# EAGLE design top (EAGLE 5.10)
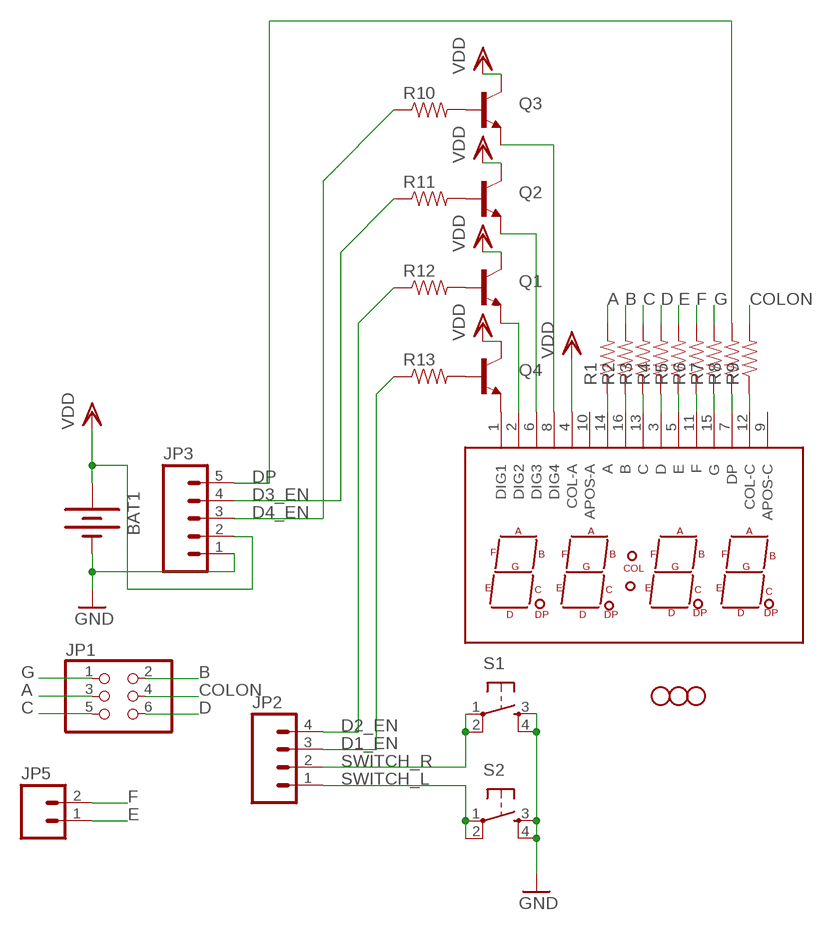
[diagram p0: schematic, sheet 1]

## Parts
BAT1  BATTERYFOB  [BATTERY_20MM_PTH_COMPACT]
JP1  PINHD-2X3  [2X03]
JP2  M04PTH  [1X04]
JP3  M05PTH  [1X05]
JP4  STAND-OFF  [STAND-OFF]
JP5  M02PTH  [1X02]
JP6  STAND-OFF  [STAND-OFF]
JP7  STAND-OFF  [STAND-OFF]
Q1  TRANSISTOR_NPNTO92  [TO-92]
Q2  TRANSISTOR_NPNTO92  [TO-92]
Q3  TRANSISTOR_NPNTO92  [TO-92]
Q4  TRANSISTOR_NPNTO92  [TO-92]
R1  RESISTORPTH-1/6W  [1/6W-RES]
R2  RESISTORPTH-1/6W  [1/6W-RES]
R3  RESISTORPTH-1/6W  [1/6W-RES]
R4  RESISTORPTH-1/6W  [1/6W-RES]
R5  RESISTORPTH-1/6W  [1/6W-RES]
R6  RESISTORPTH-1/6W  [1/6W-RES]
R7  RESISTORPTH-1/6W  [1/6W-RES]
R8  RESISTORPTH-1/6W  [1/6W-RES]
R9  RESISTORPTH-1/6W  [1/6W-RES]
R10  RESISTORPTH-1/6W  [1/6W-RES]
R11  RESISTORPTH-1/6W  [1/6W-RES]
R12  RESISTORPTH-1/6W  [1/6W-RES]
R13  RESISTORPTH-1/6W  [1/6W-RES]
S1  TAC_SWITCHPTH  [TACTILE-PTH]
S2  TAC_SWITCHPTH  [TACTILE-PTH]
U$1  7-SEGMENT-4DIGIT-YOUNGSUN  [7-SEGMENT-4DIGIT-YOUNGSUN]

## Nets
A: JP1.3 R1.2
B: JP1.2 R2.2
C: JP1.5 R3.2
COLON: JP1.4 R9.2
D: JP1.6 R4.2
D1_EN: JP2.3 R13.1
D2_EN: JP2.4 R12.1
D3_EN: JP3.4 R11.1
D4_EN: JP3.3 R10.1
DP: JP3.5 R8.2
E: JP5.1 R5.2
F: JP5.2 R6.2
G: JP1.1 R7.2
GND: BAT1.2(-) JP3.1 S1.3 S1.4 S2.3 S2.4
N$1: R1.1 U$1.14(A)
N$2: R2.1 U$1.16(B)
N$3: R3.1 U$1.13(C)
N$4: R4.1 U$1.3(D)
N$5: R5.1 U$1.5(E)
N$6: R6.1 U$1.11(F)
N$7: R7.1 U$1.15(G)
N$8: R8.1 U$1.7(DP)
N$9: Q4.1(E) U$1.1(DIG1)
N$19: R9.1 U$1.12(COL-C)
N$20: Q1.1(E) U$1.2(DIG2)
N$21: Q2.1(E) U$1.6(DIG3)
N$24: Q3.1(E) U$1.8(DIG4)
N$25: Q3.2(B) R10.2
N$26: Q2.2(B) R11.2
N$27: Q1.2(B) R12.2
N$28: Q4.2(B) R13.2
SWITCH_L: JP2.1 S2.1 S2.2
SWITCH_R: JP2.2 S1.1 S1.2
VDD: BAT1.1(+) JP3.2 Q1.3(C) Q2.3(C) Q3.3(C) Q4.3(C) U$1.4(COL-A)
Unconnected: U$1.9(APOS-C) U$1.10(APOS-A)

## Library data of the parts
BAT1 = SparkFun:BATTERY: Battery Holders
JP1 = SparkFun:PINHD-2X3: PIN HEADER
JP2 = SparkFun:M04: Header 4 Standard 4-pin 0.1" header. Use with straight break away headers (SKU : PRT-00116), right angle break away headers (PRT-00553), swiss pins (PRT-00743), machine pins (PRT-00117), and female headers (PRT-00115). Molex polarized connector foot print use with SKU : PRT-08231 with associated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
JP3 = SparkFun:M05: Header 5 Standard 5-pin 0.1" header. Use with straight break away headers (SKU : PRT-00116), right angle break away headers (PRT-00553), swiss pins (PRT-00743), machine pins (PRT-00117), and female headers (PRT-00115). Molex polarized connector foot print use with SKU : PRT-08230 with associated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
JP4 JP6 JP7 = SparkFun:STAND-OFF: Stand Off
JP5 = SparkFun:M02: Header 2
Q1-Q4 = SparkFun:TRANSISTOR_NPN: Transistor NPN BJT configuration in SOT23 package. MMBT2222 is the common NPN we use. Double check BCE configuration again layout.
R1-R13 = SparkFun:RESISTOR: Resistor
S1 S2 = SparkFun:TAC_SWITCH: Momentary Switch Button commonly used for reset or general input. Spark Fun Electronics SKU : COM-00097
U$1 = SparkFun:7-SEGMENT-4DIGIT-YOUNGSUN: This is a part for the 4-Digit 7-segment LEDs from Young Sun. Different from the Digikey LEDs, all 16 pins are used. The LONGPADS Variant is used for a test jig, but you may like it because there is more pad to solder to. If you are concerned about routing space, the standard works just fine though.

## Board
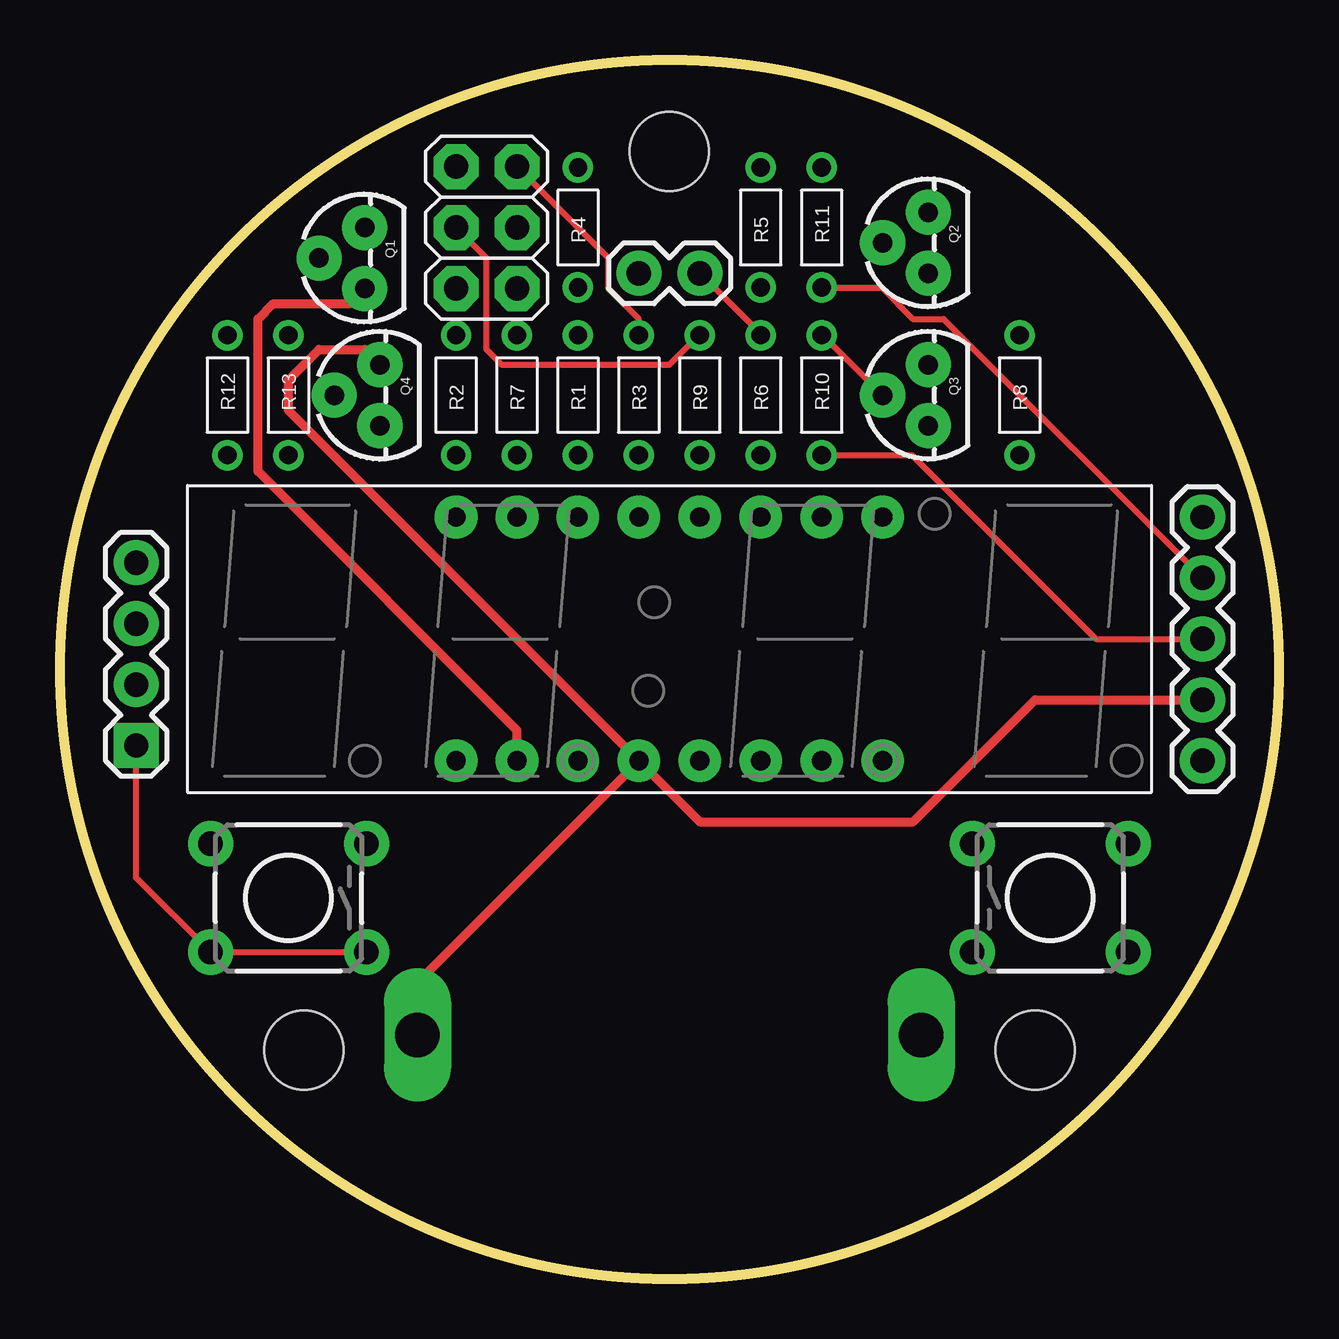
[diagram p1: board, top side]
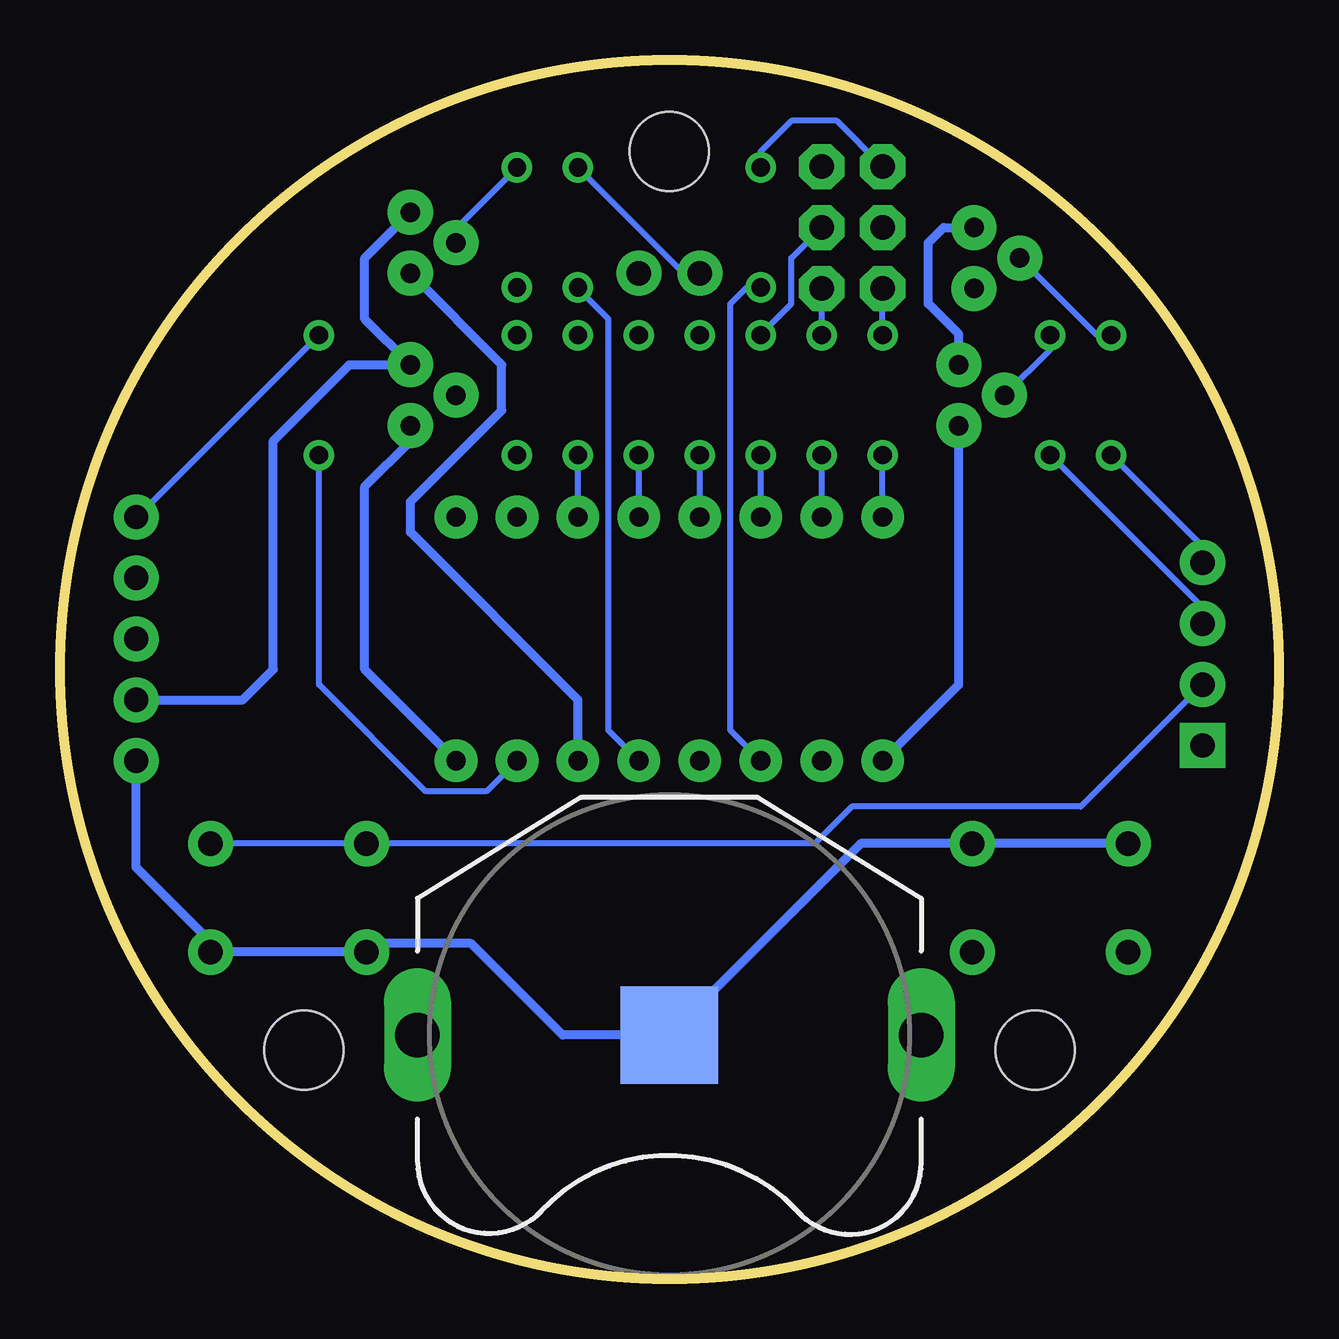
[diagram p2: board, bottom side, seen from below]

Size 50.8 x 50.8 mm. Coordinates in mm from the lower left corner, seen from the top.
Outline: circle at 25.4,25.4 radius 25.4
Copper layers (1*16): Top 0.035mm / dielectric 1.5mm / Bottom 0.035mm
Design rules "default": minimum track width 10mil, minimum drill 24mil, track to track 8mil, track to pad 8mil, pad to pad 8mil, via to via 8mil, smd to smd 8mil, copper to edge 40mil, drill to drill 8mil, minimum pad ring 10mil, minimum via ring 8mil, stop-mask expansion 4mil, vias tented up to drill 0mil, thermal gap 10mil

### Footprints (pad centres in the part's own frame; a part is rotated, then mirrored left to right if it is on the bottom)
BATTERY_20MM_PTH_COMPACT = drill 1.854 long: 1 -10.5,0; 3 10.5,0 | smd 4.064 x 4.064: 2 0,0
2X03 = drill 1.016 pad 1.88 octagon: 1 -2.54,-1.27; 2 -2.54,1.27; 3 0,-1.27; 4 0,1.27; 5 2.54,-1.27; 6 2.54,1.27
1X04 = drill 1.016 pad 1.88 square: 1 0,0 | drill 1.016 pad 1.88 round: 2 2.54,0; 3 5.08,0; 4 7.62,0
1X05 = drill 1.016 pad 1.88 round: 1 0,0; 2 2.54,0; 3 5.08,0; 4 7.62,0; 5 10.16,0
STAND-OFF = hole 3.302: 0,0
1X02 = drill 1.016 pad 1.88 round: 1 0,0; 2 2.54,0
TO-92 = drill 0.813 pad 1.88 round: 1 -1.27,0; 2 0,1.905; 3 1.27,0
1/6W-RES = drill 0.762 round: 1 -2.5,0; 2 2.5,0
TACTILE-PTH = drill 1.016 pad 1.88 round: 1 -3.251,2.261; 2 3.251,2.261; 3 -3.251,-2.261; 4 3.251,-2.261
7-SEGMENT-4DIGIT-YOUNGSUN = drill 0.8 pad 1.778 round: 1 -8.89,-5.08; 2 -6.35,-5.08; 3 -3.81,-5.08; 4 -1.27,-5.08; 5 1.27,-5.08; 6 3.81,-5.08; 7 6.35,-5.08; 8 8.89,-5.08; 9 8.89,5.08; 10 6.35,5.08; 11 3.81,5.08; 12 1.27,5.08; 13 -1.27,5.08; 14 -3.81,5.08; 15 -6.35,5.08; 16 -8.89,5.08

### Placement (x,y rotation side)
BAT1  25.4,10.16 180 bottom
JP1  17.78,43.81 90 top
JP2  3.17,22.23 90 top
JP3  47.62,21.59 90 top
JP4  25.4,46.99 0 top
JP5  24.13,41.91 0 top
JP6  10.16,9.53 0 top
JP7  40.64,9.53 0 top
Q1  12.7,42.55 90 top
Q2  36.2,43.18 90 top
Q3  36.2,36.83 90 top
Q4  13.34,36.83 90 top
R1  21.59,36.83 90 top
R2  16.51,36.83 90 top
R3  24.13,36.83 90 top
R4  21.59,43.81 90 top
R5  29.21,43.81 90 top
R6  29.21,36.83 90 top
R7  19.05,36.83 90 top
R8  40.01,36.83 90 top
R9  26.67,36.83 90 top
R10  31.75,36.83 90 top
R11  31.75,43.81 90 top
R12  6.99,36.83 90 top
R13  9.53,36.83 90 top
S1  41.27,15.88 0 top
S2  9.53,15.88 180 top
U$1  25.4,26.67 0 top

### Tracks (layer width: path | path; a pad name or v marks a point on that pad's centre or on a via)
A
  Bottom 0.254: R1.2 21.59,39.37 20.32,40.64 20.32,42.55 JP1.3
B
  Bottom 0.254: R2.2 JP1.2
C
  Top 0.254: R3.2 24.13,40.01 22.86,41.27 22.86,42.55 JP1.5
COLON
  Top 0.254: R9.2 26.63,39.33 25.4,38.1 18.41,38.1 17.78,38.73 17.78,42.55 JP1.4
D
  Bottom 0.254: R4.2 21.59,46.99 20.32,48.26 18.41,48.26 JP1.6
D1_EN
  Bottom 0.254: JP2.3 3.17,27.98 R13.1
D2_EN
  Bottom 0.254: JP2.4 3.17,30.52 R12.1
D3_EN
  Top 0.254: R11.1 34.25,41.31 35.56,40.01 36.83,40.01 JP3.4
D4_EN
  Top 0.254: R10.1 35.52,34.33 43.18,26.67 JP3.3
DP
  Bottom 0.254: JP3.5 47.59,31.75 R8.2
E
  Bottom 0.254: JP5.1 24.8,41.91 R5.2
F
  Top 0.254: R6.2 29.21,39.37 JP5.2
G
  Bottom 0.254: R7.2 JP1.1
GND
  Bottom 0.381: S2.4 S2.3 17.42,18.14 BAT1.2 29.84,10.16 33.66,13.97 37.67,13.97 S1.3 S1.4 44.53,14.05 47.62,17.14 JP3.1
N$1
  Bottom 0.254: U$1.14 R1.1
N$2
  Bottom 0.254: U$1.16 R2.1
N$3
  Bottom 0.254: U$1.13 R3.1
N$4
  Bottom 0.254: R4.1 22.18,41.31 22.86,40.64 22.86,22.86 U$1.3
N$5
  Bottom 0.254: R5.1 29.21,41.27 27.94,40.01 27.94,22.86 U$1.5
N$6
  Bottom 0.254: U$1.11 R6.1
N$7
  Bottom 0.254: U$1.15 R7.1
N$8
  Bottom 0.254: R8.1 40.01,24.77 35.56,20.32 33.02,20.32 U$1.7
N$9
  Bottom 0.381: Q4.1 13.34,24.77 U$1.1
N$19
  Bottom 0.254: U$1.12 R9.1
N$20
  Top 0.381: U$1.2 19.05,22.86 8.26,33.66 8.26,40.01 8.89,40.64 12.06,40.64 Q1.1
N$21
  Bottom 0.381: U$1.6 29.21,24.13 36.2,31.11 36.2,32.38 32.38,36.2 32.38,38.1 Q2.1
N$24
  Bottom 0.381: Q3.1 36.2,34.92 38.1,33.02 38.1,25.4 U$1.8
N$25
  Top 0.254: R10.2 31.79,39.33 Q3.2
N$26
  Bottom 0.254: Q2.2 34.29,43.77 R11.2
N$27
  Bottom 0.254: R12.2 7.58,39.33 Q1.2
N$28
  Bottom 0.254: R13.2 9.53,38.73 Q4.2
SWITCH_L
  Top 0.254: JP2.1 3.17,16.71 S2.2 S2.1
SWITCH_R
  Bottom 0.254: S1.2 S1.1 19.33,18.14 17.78,19.68 8.26,19.68 JP2.2
VDD
  Top 0.381: U$1.4 9.53,36.2 9.53,37.47 10.79,38.73 12.7,38.73 Q4.3 | U$1.4 26.67,19.05 35.56,19.05 40.64,24.13 JP3.2 | BAT1.1 14.9,12.36 U$1.4
  Bottom 0.381: Q4.3 13.34,39.37 14.61,40.64 14.61,43.18 13.97,43.81 Q1.3 | Q2.3 38.1,42.55 38.1,40.01 Q3.3 38.73,38.1 41.91,34.92 41.91,25.4 43.18,24.13 JP3.2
